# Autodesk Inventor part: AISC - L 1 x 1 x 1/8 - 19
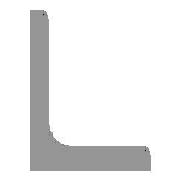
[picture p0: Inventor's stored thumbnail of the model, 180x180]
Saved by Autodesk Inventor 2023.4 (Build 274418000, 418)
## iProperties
Created: 2023-10
Part Number: AISC - L 1 x 1 x 1/8 - 19
Material: Steel, Mild
Description: Angle Steel
Document SubType Name: Modeling
Standard: AISC
Designer: Fred L.
Standards Organization: ANSI
Language: en-US
Size Designation: (L 1 x 1 x 1/8)
Categories: <MemberInstance><Categories><Category DisplayName="Structural Shapes" InternalName="089c4875-fa83-4c05-b084-43b9cc11f5ed" Mnemonic="GRDR"><CategoryParameter Dis
Stock Number: (L 1 x 1 x 1/8)
Mass: 577.931 g
Surface Area: 480.22 cm^2
Volume: 73.6218 cm^3
Density: 7.85 g/cm^3
Appearance: Semi-Polished
IsCustomPart: 1
G_L: 19.000 in
G_W: 1.000 in
G_H: 1.000 in
Mass: 1.27
SurfaceArea: 74.43
+BC6EA230-662A-4952-B540-0E13420F9ACB+CUTDETAIL1: Corner Joint
+C1146D65-74C9-4788-BE2C-8E1DC69530BD+CUTDETAIL2: Corner Joint
_CCFamilyMember: 1
_CCFamilyDisplayName: ANSI L (Equal angles) - Angle Steel — Sizes in parentheses have been withdrawn
_FrameMemberDoc: Frame Member File
_Version: 25.0.0
_GetPNFromCC: 1
Author: Fred L.
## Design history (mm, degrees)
node "Start Plane"
node "End Plane"
sketch "Sketch"
  geometry: L1 (25.4, 0)-(0, 0); L2 (0, 0)-(0, 25.4); L3 (0, 25.4)-(1.651, 25.4); L4 (3.175, 23.876)-(3.175, 6.477); L5 (6.477, 3.175)-(23.876, 3.175); L6 (25.4, 1.651)-(25.4, 0); L7 (0, -11.041)-(0, 31.538); L8 (-11.041, 0)-(31.538, 0); L9 (0, 40.054)-(0, -19.557) reference; L10 (-19.557, 0)-(40.054, 0) reference; A1 r 3.302 centre (6.477, 6.477) between (3.175, 6.477) and (6.477, 3.175); A2 r 1.524 centre (1.651, 23.876) between (3.175, 23.876) and (1.651, 25.4); A3 r 1.524 centre (23.876, 1.651) between (25.4, 1.651) and (23.876, 3.175); 3 further points
  constraints: 16 end point, 6 point on circle, 6 point on line, 6 tangent, 4 parallel, 3 centre point, 2 collinear, 1 equal radius, 1 horizontal, 1 perpendicular
  dimensions: "d0" = 25.4 distance between parallel lines of L6 L2 (= G_H); "d1" = 25.4 distance between parallel lines of L3 L1 (= G_H); "d2" = 3.175 distance between parallel lines of L2 L4 (= G_T); "d3" = 3.175 distance between parallel lines of L1 L5 (= G_T); "d10" = 0 distance between parallel lines of L7 L2 (computed from ex); "d11" = 0 distance between parallel lines of L8 L1 (computed from d10); "d14" = 3.302 radius of A1 (= G_IR); "d15" = 1.524 radius of A2 (= G_ER)
extrude "Body" new body sketch "Sketch" stored distance "d4" = 482.6 (= G_L); taper "d5" = 0 deg
node "Driven Length"
  sketch "Sketch3"
    geometry: L1 (0, 0)-(10, 0) reference
    constraints: 2 end point, 1 horizontal
  workplane "Work Plane3"
workplane "Work Plane4"
split "Split1"
workplane "Work Plane5"
split "Split2"
body "Solid1"
sketch "Sketch4"
  geometry: L1 (-2, 12.7)-(12, 12.7) reference; L2 (-2, 495.3)-(12, 495.3) reference
  dimensions: "d17" = 482.6 distance between parallel lines of L1 L2 (derived)
other parameters: "G_H" = 25.4 [user parameter; used in 2 equation terms], "G_T" = 3.175 [user parameter; used in 2 equation terms], "G_ER" = 1.524 [user parameter; used in 1 equation term], "G_IR" = 3.302 [user parameter; used in 1 equation term], "G_L" = 482.6 (= d17) [user parameter; used in 1 equation term], "ex" = 0 [user parameter; used in 1 equation term], "G_OFFSET_START" = -12.7 [user parameter; used in 1 equation term], "G_OFFSET_END" = -12.7 [user parameter; used in 1 equation term], "d12" = 12.7 (= -G_OFFSET_START), "d13" = 495.3 (= G_OFFSET_END + B_L), "B_L" = 508 [user parameter; used in 1 equation term], "d16" = 90 deg, "MAS" = 0.11905 [user parameter]
